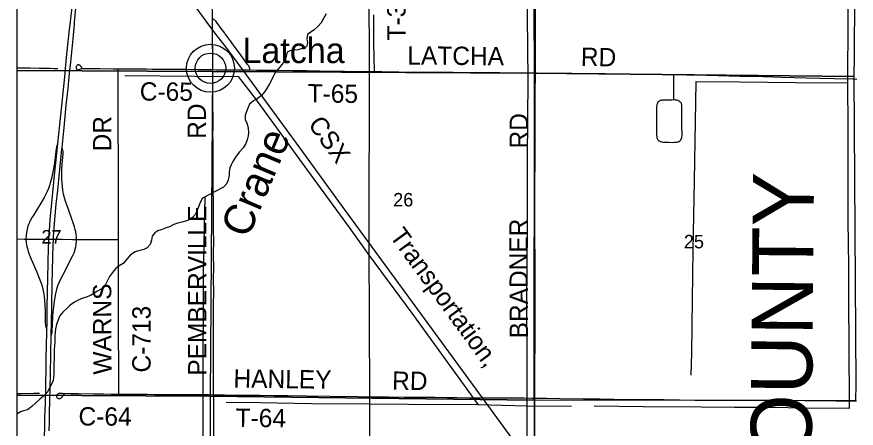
# Model space of a CAD drawing. Extents: x 0 to 34, y 0 to 22.
# Drawn here: x 2.1 to 4.702, y 15.265 to 16.541 of the extents above; entities that cross this region are included whole.
import ezdxf

# ---------------------------------------------------------------- set-up
doc = ezdxf.new("R2010")
doc.units = 0
for name, color, linetype in [('Default', 7, 'Continuous'), ('GM_X_County_Road', 7, 'Continuous'), ('GM_X_County_Road_Text', 7, 'Continuous'), ('GM_X_County_Text', 7, 'Continuous'), ('GM_X_Interchange_Ramps', 7, 'Continuous'), ('GM_X_Interstate_Route', 7, 'Continuous'), ('GM_X_Minor_River', 7, 'Continuous'), ('GM_X_Minor_River_Text', 7, 'Continuous'), ('GM_X_Rail_Line', 7, 'Continuous'), ('GM_X_Rail_Line_Text', 7, 'Continuous'), ('GM_X_Section', 7, 'Continuous'), ('GM_X_Section_Text', 7, 'Continuous'), ('GM_X_Township_Road', 7, 'Continuous'), ('GM_X_Township_Road_Text', 7, 'Continuous'), ('GM_X_Unincorporated', 7, 'Continuous'), ('GM_X_Unincorporated_Location', 7, 'Continuous'), ('GM_X_Unincorporated_Text', 7, 'Continuous')]:
    doc.layers.add(name, color=color, linetype=linetype)

msp = doc.modelspace()

# ---------------------------------------------------------------- linework, layer by layer
at = {"layer": 'Default'}
for points in [[(2.1, 17.3903), (2.1, 16.375), (2.7079, 16.3715), (2.7017, 17.3873)], [(2.1, 16.375), (2.1, 15.3673), (2.7001, 15.3638), (2.7079, 16.3715)], [(2.1, 15.3673), (2.1, 14.3654), (2.6651, 14.3602), (2.7019, 14.3602), (2.7001, 15.3638)]]:
    msp.add_lwpolyline(points, close=True, dxfattribs=at)
at = {"layer": 'GM_X_County_Road'}
for points in [[(2.7069, 16.5346), (2.7069, 16.5391), (2.7066, 16.5708)], [(2.7076, 16.3773), (2.7074, 16.4154), (2.7069, 16.467), (2.7066, 16.4956), (2.7067, 16.5062), (2.7069, 16.5161), (2.7069, 16.5346)], [(2.1, 16.3831), (2.1106, 16.3831), (2.1417, 16.3829), (2.1691, 16.3823), (2.1902, 16.3821), (2.2032, 16.3817), (2.2156, 16.3812), (2.2274, 16.3808)], [(2.3025, 16.3814), (2.3009, 16.3844), (2.2995, 16.3867), (2.2985, 16.3881), (2.297, 16.3898), (2.2956, 16.3908), (2.2941, 16.3915), (2.2925, 16.3919), (2.2908, 16.3919), (2.2892, 16.3915), (2.2877, 16.3908), (2.2864, 16.3898), (2.2853, 16.3886), (2.2844, 16.3871), (2.2838, 16.3855), (2.2836, 16.3839), (2.2837, 16.3823), (2.2841, 16.3813), (2.2845, 16.3805), (2.2853, 16.3796), (2.2864, 16.3787), (2.2878, 16.3779), (2.2894, 16.3774), (2.2909, 16.3773), (2.2927, 16.3774), (2.2949, 16.3779), (2.2966, 16.3787), (2.2981, 16.3795), (2.3002, 16.3806), (2.3021, 16.381), (2.3041, 16.3811), (2.308, 16.3812), (2.3128, 16.3812), (2.3235, 16.3812), (2.3446, 16.3808), (2.3583, 16.3805), (2.3993, 16.3802), (2.4145, 16.3801)], [(2.4154, 15.85), (2.4152, 15.9045), (2.415, 15.9897), (2.415, 16.0438), (2.4149, 16.1078), (2.4147, 16.185), (2.4146, 16.2465), (2.4144, 16.3317), (2.4145, 16.3697), (2.4145, 16.3801)], [(2.4145, 16.3801), (2.4316, 16.3799), (2.4538, 16.3797)], [(2.4538, 16.3797), (2.4739, 16.3796), (2.5006, 16.3794), (2.5211, 16.3793), (2.5659, 16.379), (2.5883, 16.3789), (2.6243, 16.3784), (2.6622, 16.3779), (2.6872, 16.3777), (2.7076, 16.3773)], [(2.7102, 15.3684), (2.7098, 15.3851), (2.7102, 15.4354), (2.7101, 15.4993), (2.7101, 15.5404), (2.71, 15.5833), (2.7103, 15.6475), (2.7106, 15.6878), (2.7102, 15.7257), (2.7104, 15.7667), (2.7103, 15.7985), (2.7105, 15.8544), (2.7103, 15.8675), (2.7102, 15.8868), (2.7103, 15.8986), (2.7099, 15.9272), (2.7096, 15.9693), (2.7093, 16.0015), (2.7089, 16.0178), (2.7085, 16.0544), (2.7089, 16.103), (2.7085, 16.1508), (2.7083, 16.1756), (2.7084, 16.198), (2.7085, 16.2323), (2.7082, 16.2596), (2.7079, 16.2926), (2.7078, 16.3087), (2.7076, 16.3199), (2.7076, 16.3553), (2.7076, 16.3773)], [(2.1, 15.8518), (2.1227, 15.8516), (2.1276, 15.8516)], [(2.1276, 15.8516), (2.1495, 15.8516), (2.1843, 15.8511), (2.1996, 15.8511), (2.2138, 15.851), (2.2402, 15.8509), (2.2731, 15.8507), (2.2855, 15.8507)], [(2.2855, 15.8507), (2.3005, 15.8506), (2.3408, 15.8503), (2.4154, 15.85)], [(2.416, 15.3705), (2.4161, 15.3796), (2.4161, 15.392), (2.4159, 15.4586), (2.4157, 15.555), (2.4157, 15.5935), (2.4156, 15.6906), (2.4157, 15.7328), (2.4154, 15.7614), (2.4156, 15.7813), (2.4155, 15.8242), (2.4154, 15.85)], [(2.1, 15.3724), (2.1134, 15.3724), (2.1519, 15.3732), (2.1657, 15.3734), (2.1706, 15.3735)], [(2.2478, 15.3723), (2.2473, 15.3716), (2.2432, 15.3657), (2.2418, 15.3638), (2.2399, 15.3611), (2.2378, 15.3585), (2.2366, 15.3573), (2.2353, 15.3564), (2.2337, 15.3558), (2.2321, 15.3555), (2.2305, 15.3557), (2.2289, 15.3562), (2.2275, 15.357), (2.2262, 15.3582), (2.2252, 15.3595), (2.2245, 15.3611), (2.2241, 15.3627), (2.224, 15.3644), (2.2242, 15.3661), (2.2248, 15.3677), (2.2256, 15.3691), (2.2266, 15.3704), (2.2279, 15.3714), (2.2294, 15.3722), (2.2316, 15.3729), (2.2346, 15.3732), (2.242, 15.3731), (2.2668, 15.3722), (2.2818, 15.3719), (2.2911, 15.3719), (2.3377, 15.3714), (2.3551, 15.3713), (2.37, 15.371), (2.3918, 15.3706), (2.416, 15.3705)], [(2.416, 15.3705), (2.4229, 15.3705), (2.4847, 15.3701)], [(2.4847, 15.3701), (2.5056, 15.37), (2.5274, 15.3696), (2.5821, 15.3695), (2.6461, 15.3691), (2.6716, 15.369), (2.6942, 15.3688), (2.708, 15.3684), (2.7102, 15.3684)], [(2.7076, 14.7538), (2.7078, 14.762), (2.7081, 14.8136), (2.7085, 14.8357), (2.7085, 14.8418), (2.7086, 14.8505), (2.7087, 14.8596), (2.7087, 14.865), (2.7088, 14.8824), (2.7089, 14.9074), (2.7092, 14.9316), (2.7091, 14.954), (2.7095, 14.9764), (2.7111, 15.064), (2.7116, 15.0914), (2.7115, 15.1045), (2.7116, 15.1337), (2.7116, 15.1902), (2.7112, 15.2413), (2.7105, 15.319), (2.7106, 15.3539), (2.7102, 15.3684)]]:
    msp.add_lwpolyline(points, dxfattribs=at)
at = {"layer": 'GM_X_Interchange_Ramps'}
for points in [[(2.227, 16.1478), (2.2252, 16.1439), (2.224, 16.1404), (2.2229, 16.1371), (2.222, 16.1329), (2.218, 16.0964), (2.2161, 16.0823), (2.214, 16.0701), (2.2109, 16.0548), (2.2072, 16.0391), (2.2039, 16.0265), (2.2015, 16.0182), (2.1982, 16.0088), (2.1945, 15.9996), (2.1904, 15.9905), (2.185, 15.9801), (2.1777, 15.9678), (2.1597, 15.9388), (2.1525, 15.9271), (2.1476, 15.9191), (2.1425, 15.9104), (2.1407, 15.9068)], [(2.2855, 15.8507), (2.2848, 15.8583), (2.2841, 15.8664), (2.283, 15.8738), (2.2813, 15.8817), (2.2792, 15.8894), (2.276, 15.8989), (2.2609, 15.9397), (2.2547, 15.9573), (2.251, 15.9691), (2.248, 15.9799), (2.2453, 15.9914), (2.2431, 16.0037), (2.2416, 16.0147), (2.2405, 16.0259), (2.2398, 16.0383), (2.2396, 16.0513), (2.24, 16.0663), (2.241, 16.0843), (2.2435, 16.1165), (2.2436, 16.1196), (2.2434, 16.1233), (2.2428, 16.1271), (2.2417, 16.1316), (2.2403, 16.136)], [(2.1407, 15.9068), (2.139, 15.9033), (2.1363, 15.8966), (2.1337, 15.8888), (2.1317, 15.881), (2.1299, 15.8718), (2.1286, 15.8631), (2.1276, 15.8516)], [(2.1276, 15.8516), (2.129, 15.8402), (2.1298, 15.834), (2.1309, 15.8285), (2.1327, 15.8219), (2.1356, 15.8131), (2.1386, 15.8049), (2.1418, 15.7968), (2.1522, 15.7729), (2.1619, 15.7493), (2.1719, 15.7246), (2.1753, 15.7152), (2.1782, 15.7057), (2.1807, 15.6961), (2.1828, 15.6858), (2.1848, 15.6735), (2.1863, 15.6605), (2.1871, 15.6463), (2.1876, 15.6276), (2.1881, 15.5916), (2.1891, 15.5836), (2.19, 15.5796), (2.1911, 15.5759), (2.1933, 15.5697)], [(2.271, 15.7949), (2.2751, 15.803), (2.2777, 15.8089), (2.2797, 15.8145), (2.2815, 15.8212), (2.2831, 15.8279), (2.2843, 15.8346), (2.2852, 15.8443), (2.2855, 15.8507)], [(2.2067, 15.5518), (2.209, 15.5578), (2.2098, 15.5618), (2.2102, 15.5662), (2.211, 15.5872), (2.2119, 15.6083), (2.2131, 15.6251), (2.2148, 15.6412), (2.2169, 15.6578), (2.219, 15.6713), (2.2212, 15.6829), (2.2233, 15.6914), (2.2256, 15.6998), (2.2288, 15.7092), (2.2327, 15.719), (2.237, 15.7286), (2.2435, 15.7414), (2.2575, 15.7677), (2.271, 15.7949)]]:
    msp.add_lwpolyline(points, dxfattribs=at)
at = {"layer": 'GM_X_Interstate_Route'}
for points in [[(4.7088, 20.9), (2.1, 20.9), (2.1, 14.3639)], [(2.2664, 16.5242), (2.2678, 16.5361), (2.2863, 16.6892), (2.2911, 16.7324), (2.2947, 16.7671), (2.2976, 16.7949), (2.3097, 16.9117), (2.3139, 16.9538), (2.3177, 16.9909), (2.3235, 17.0459), (2.3279, 17.0899), (2.3333, 17.1443), (2.3431, 17.237), (2.3464, 17.2717), (2.3468, 17.2766)], [(2.2787, 16.5175), (2.2794, 16.5245), (2.2831, 16.5685), (2.2888, 16.6361), (2.2917, 16.6695), (2.2939, 16.6937), (2.2993, 16.7519), (2.3027, 16.7865), (2.3057, 16.8156), (2.3146, 16.8996), (2.3198, 16.9503), (2.3242, 16.9943), (2.3297, 17.0493), (2.3341, 17.0926), (2.3388, 17.1365), (2.3464, 17.2113), (2.352, 17.2639), (2.3534, 17.2758)], [(2.1857, 15.2086), (2.1874, 15.2981), (2.1885, 15.3416), (2.1899, 15.4001), (2.1909, 15.4492), (2.1914, 15.4902), (2.1919, 15.5126), (2.1933, 15.5697), (2.1938, 15.5903), (2.1942, 15.6089), (2.1945, 15.6319), (2.1957, 15.6947), (2.1962, 15.7227), (2.1974, 15.7855), (2.1982, 15.8178), (2.1996, 15.8511), (2.2011, 15.8786), (2.2035, 15.9121), (2.2061, 15.9418), (2.2167, 16.0501), (2.2209, 16.0884), (2.227, 16.1478), (2.233, 16.2065), (2.2495, 16.3658), (2.2499, 16.3692), (2.2556, 16.4255), (2.2637, 16.5015), (2.2664, 16.5242)], [(2.2007, 15.2563), (2.2012, 15.285), (2.2018, 15.3117), (2.2034, 15.3919), (2.2043, 15.431), (2.2054, 15.4957), (2.2067, 15.5518), (2.2077, 15.5926), (2.2087, 15.6442), (2.2101, 15.7132), (2.2119, 15.7947), (2.213, 15.8332), (2.2138, 15.851), (2.2142, 15.8587), (2.2161, 15.8879), (2.2189, 15.9238), (2.2223, 15.9598), (2.227, 16.003), (2.2304, 16.0339), (2.2348, 16.0791), (2.2396, 16.1292), (2.2403, 16.136), (2.2466, 16.1973), (2.2536, 16.2672), (2.2589, 16.3185), (2.2639, 16.3659), (2.2676, 16.4008), (2.2745, 16.4725), (2.2787, 16.5175)]]:
    msp.add_lwpolyline(points, dxfattribs=at)
at = {"layer": 'GM_X_Minor_River'}
for points in [[(3.6785, 17.0216), (3.6816, 16.7654), (3.6827, 16.5423), (3.6841, 16.3464), (3.6825, 16.1017), (3.6821, 15.8805), (3.6804, 15.6582), (3.6808, 15.4396), (3.6814, 15.3334), (3.6828, 15.1345), (3.683, 15.0055), (3.6833, 14.8112), (3.6833, 14.6667)], [(4.7006, 17.0285), (4.6915, 17.0258), (4.6859, 17.0213), (4.6828, 17.0141), (4.6803, 17.002), (4.6792, 16.9527), (4.6799, 16.81), (4.6773, 16.6662), (4.6768, 16.4928), (4.6751, 16.3793), (4.6751, 16.3346), (4.6764, 16.1979), (4.6763, 16.0257), (4.6763, 15.9088), (4.6786, 15.7672), (4.6786, 15.6466), (4.6794, 15.5312), (4.6803, 15.3255), (4.5472, 15.3266), (4.4349, 15.3284), (4.3256, 15.329), (4.2223, 15.3295), (4.0419, 15.3313), (3.8902, 15.3326)], [(3.1937, 14.6594), (3.1937, 14.9), (3.1943, 15.1508), (3.1942, 15.339), (3.1938, 15.6247), (3.1921, 15.8008), (3.1928, 16.0148), (3.1938, 16.2242), (3.194, 16.3798), (3.1923, 16.6356), (3.1907, 16.6743), (3.1894, 16.725)], [(3.059, 16.5508), (3.0504, 16.5365), (3.0438, 16.5226), (3.0334, 16.511), (3.0223, 16.501), (3.0116, 16.4935), (3.0016, 16.4861), (2.9991, 16.4729), (3.0008, 16.4607), (2.998, 16.4486), (2.9847, 16.4427), (2.9725, 16.4391), (2.9619, 16.4374), (2.9501, 16.4368), (2.9383, 16.4317), (2.9355, 16.4189), (2.9319, 16.406), (2.9222, 16.3929), (2.9103, 16.379), (2.9002, 16.3659), (2.8944, 16.3562), (2.8885, 16.343), (2.8834, 16.3328), (2.8776, 16.3227), (2.8694, 16.3099), (2.8587, 16.2972), (2.8456, 16.2871), (2.8334, 16.2801), (2.8219, 16.27), (2.8161, 16.258), (2.8113, 16.2448), (2.8081, 16.235), (2.8079, 16.2225), (2.8141, 16.2091), (2.8173, 16.1961), (2.8179, 16.1813), (2.8173, 16.1715), (2.8145, 16.159), (2.8102, 16.1484), (2.802, 16.1345), (2.7908, 16.1226), (2.78, 16.1087), (2.7696, 16.0925), (2.7649, 16.082), (2.7605, 16.0722), (2.7584, 16.059), (2.7583, 16.0495), (2.7558, 16.0351), (2.7507, 16.0245), (2.7411, 16.0129), (2.6762, 15.9787), (2.6688, 15.9652), (2.6629, 15.952), (2.659, 15.941), (2.6539, 15.9293), (2.6446, 15.9185), (2.6324, 15.91), (2.6229, 15.9071), (2.6122, 15.9035), (2.5997, 15.9014), (2.5864, 15.8967), (2.573, 15.8893), (2.5632, 15.8864), (2.5476, 15.8802), (2.5377, 15.8766), (2.5281, 15.8707), (2.5193, 15.8609), (2.5172, 15.8477), (2.5132, 15.8349), (2.5043, 15.8248), (2.494, 15.8196), (2.4773, 15.8146), (2.4667, 15.8117), (2.4525, 15.8021), (2.4302, 15.7759), (2.4179, 15.7689), (2.4064, 15.7588), (2.3964, 15.7476), (2.3879, 15.7356), (2.3813, 15.7232), (2.375, 15.7104), (2.3642, 15.6984), (2.3505, 15.6899), (2.339, 15.6825), (2.3287, 15.6766), (2.3146, 15.6715), (2.3047, 15.6682), (2.2907, 15.6624), (2.2792, 15.6554)], [(2.4352, 16.359), (2.6534, 16.357), (2.7866, 16.356), (2.8392, 16.2876), (3.0014, 16.0645), (3.1306, 15.8879), (3.1921, 15.8008), (3.3243, 15.6214), (3.4435, 15.4567), (3.5309, 15.3366)], [(4.6759, 16.3349), (4.5147, 16.3368), (4.3411, 16.3381), (4.2049, 16.3391), (4.203, 16.2162), (4.2001, 16.0326), (4.1959, 15.8175), (4.1939, 15.6639), (4.1917, 15.4981), (4.1902, 15.4291)], [(2.6723, 14.3408), (2.6826, 14.3691), (2.6813, 14.5774), (2.6793, 14.9534), (2.6777, 15.2084), (2.6779, 15.3894), (2.6785, 15.7411), (2.6841, 15.9829)], [(2.2792, 15.6554), (2.2658, 15.6465), (2.2558, 15.6375), (2.2432, 15.6244), (2.2324, 15.6121), (2.228, 15.6012), (2.2236, 15.5868), (2.2204, 15.5725), (2.2187, 15.5615), (2.2182, 15.5512), (2.2177, 15.5433), (2.2175, 15.5327), (2.2169, 15.5205), (2.2164, 15.5092), (2.2144, 15.4341), (2.2139, 15.4238), (2.2133, 15.4121), (2.1942, 15.3752), (2.1827, 15.3644), (2.1715, 15.3543), (2.1593, 15.3431), (2.1462, 15.332), (2.1332, 15.3219), (2.1207, 15.3187), (2.1112, 15.3158), (2.1, 15.3083)], [(3.8194, 15.3323), (3.6814, 15.3334), (3.5309, 15.3366), (3.3145, 15.3382), (3.1942, 15.339), (3.0142, 15.3407), (2.855, 15.3433), (2.7494, 15.3439)]]:
    msp.add_lwpolyline(points, dxfattribs=at)
at = {"layer": 'GM_X_Rail_Line'}
msp.add_lwpolyline([(4.4636, 14.1), (4.2829, 14.3475), (4.0202, 14.7061), (3.9178, 14.8467), (3.7641, 15.0572), (3.5439, 15.3588), (3.2112, 15.8143), (3.0989, 15.9678), (2.9869, 16.1219), (2.8009, 16.3767), (2.7485, 16.4478), (2.7239, 16.4783), (2.6984, 16.5122), (2.4472, 16.8567), (2.3237, 17.0297), (2.1, 17.3362)], dxfattribs=at)
at = {"layer": 'GM_X_Section'}
for points in [[(3.7003, 17.3796), (3.7046, 16.3661), (2.7079, 16.3715), (2.7017, 17.3873)], [(4.6959, 16.4195), (4.6953, 16.3562), (3.7046, 16.3661), (3.7003, 17.3796), (4.7018, 17.3475)], [(2.7079, 16.3715), (3.7046, 16.3661), (3.7036, 15.3519), (2.7001, 15.3638)], [(3.7046, 16.3661), (4.6953, 16.3562), (4.7008, 15.401), (4.7006, 15.3495), (3.7036, 15.3519)], [(3.7036, 15.3519), (3.7061, 14.3445), (3.6799, 14.3459), (2.7019, 14.3602), (2.7001, 15.3638)]]:
    msp.add_lwpolyline(points, close=True, dxfattribs=at)
at = {"layer": 'GM_X_Township_Road'}
for points in [[(3.7078, 16.3671), (3.7078, 16.3913), (3.708, 16.4435), (3.7083, 16.4877), (3.7081, 16.5778), (3.7078, 16.6593), (3.7076, 16.7091), (3.7074, 16.7644), (3.7071, 16.8378), (3.707, 16.8988), (3.707, 16.9516), (3.7063, 17.0194), (3.7057, 17.0399), (3.7048, 17.0859), (3.7046, 17.1244), (3.7037, 17.2457), (3.7031, 17.3184)], [(2.823, 16.3764), (2.8225, 16.3789), (2.8221, 16.3813), (2.8214, 16.3836), (2.8204, 16.3861), (2.8189, 16.3887), (2.8173, 16.3911), (2.8155, 16.3938), (2.8104, 16.4009), (2.7955, 16.4209), (2.7749, 16.449), (2.7718, 16.4533), (2.7692, 16.457), (2.7625, 16.4663), (2.7603, 16.4693), (2.7586, 16.4717), (2.755, 16.4765), (2.7463, 16.4882), (2.7446, 16.4904), (2.7341, 16.5048), (2.7206, 16.5235), (2.718, 16.5269), (2.716, 16.5292), (2.7138, 16.5312), (2.712, 16.5323), (2.7095, 16.5335), (2.7069, 16.5346)], [(3.2087, 16.3713), (3.2086, 16.3779), (3.2079, 16.4109), (3.2071, 16.4651), (3.2068, 16.5473)], [(2.7076, 16.3773), (2.7169, 16.3772), (2.7453, 16.377), (2.777, 16.3767), (2.792, 16.3766), (2.8, 16.3766), (2.8174, 16.3765), (2.823, 16.3764)], [(2.823, 16.3764), (2.8442, 16.3761), (2.9051, 16.3755), (2.9555, 16.3748), (2.9978, 16.3744), (3.0388, 16.3736), (3.1942, 16.3714), (3.2087, 16.3713)], [(3.2087, 16.3713), (3.2315, 16.3711), (3.2844, 16.3707), (3.3851, 16.3698), (3.4057, 16.3699), (3.4249, 16.3696), (3.4529, 16.3691), (3.4884, 16.3688), (3.5213, 16.3685), (3.5506, 16.3685), (3.5792, 16.3681), (3.5966, 16.368), (3.6737, 16.3673), (3.701, 16.3672), (3.7078, 16.3671)], [(3.7061, 15.3581), (3.7061, 15.3615), (3.7059, 15.3876), (3.7063, 15.4175), (3.7065, 15.4366), (3.7064, 15.467), (3.7069, 15.5224), (3.7068, 15.551), (3.7068, 15.5969), (3.707, 15.6565), (3.7071, 15.7056), (3.7069, 15.7329), (3.707, 15.7566), (3.7067, 15.8131), (3.7066, 15.8299), (3.7064, 15.8629), (3.7065, 15.8884), (3.7064, 15.9282), (3.7064, 15.9798), (3.7066, 16.037), (3.7067, 16.0842), (3.7069, 16.1178), (3.7072, 16.175), (3.7074, 16.2067), (3.7073, 16.262), (3.7076, 16.3217), (3.7079, 16.3473), (3.7078, 16.3648), (3.7078, 16.3671)], [(3.7078, 16.3671), (3.711, 16.3671), (3.729, 16.3669), (3.7819, 16.3663), (3.8204, 16.366), (3.8559, 16.3657), (3.8919, 16.3653), (3.9249, 16.365), (3.9696, 16.3644), (3.9995, 16.364), (4.0281, 16.3637), (4.0548, 16.3633), (4.1102, 16.3627), (4.1369, 16.3622)], [(4.1369, 16.3622), (4.1773, 16.3614), (4.2016, 16.361), (4.2743, 16.3595), (4.3415, 16.3576), (4.3868, 16.3566), (4.4714, 16.3543), (4.5472, 16.3522), (4.6343, 16.35), (4.6922, 16.3484), (4.6964, 16.3483), (4.704, 16.3481)], [(4.1373, 16.2832), (4.1373, 16.2878), (4.1373, 16.2921), (4.1373, 16.2957), (4.1375, 16.3104), (4.1372, 16.3241), (4.1371, 16.3354), (4.1371, 16.3454), (4.1369, 16.3537), (4.1369, 16.3609), (4.1369, 16.3622)], [(4.1373, 16.2832), (4.1312, 16.283), (4.1259, 16.2828), (4.1205, 16.2826), (4.1156, 16.2826), (4.1021, 16.2826), (4.0998, 16.2824), (4.0977, 16.282), (4.0963, 16.2816), (4.0949, 16.2811), (4.0932, 16.2804), (4.0915, 16.2795), (4.0901, 16.2786), (4.0893, 16.2779), (4.0886, 16.2771), (4.0879, 16.2762), (4.0869, 16.2746), (4.0859, 16.2727), (4.0854, 16.2715), (4.0847, 16.2692), (4.0841, 16.2657), (4.0838, 16.2614), (4.0837, 16.2575), (4.0837, 16.2526), (4.0835, 16.2357), (4.0835, 16.2255), (4.0836, 16.2172), (4.0835, 16.2008), (4.0834, 16.184), (4.0833, 16.1796), (4.0834, 16.1766), (4.0836, 16.1742), (4.084, 16.1694), (4.0846, 16.1664), (4.0855, 16.1636), (4.0865, 16.1616), (4.0874, 16.1601), (4.0884, 16.1588), (4.0893, 16.1578), (4.0904, 16.1569), (4.0917, 16.1559), (4.0935, 16.155), (4.0957, 16.1541), (4.0985, 16.1532), (4.1021, 16.1527), (4.1062, 16.1524), (4.1108, 16.1521), (4.1213, 16.1518)], [(4.1213, 16.1518), (4.1314, 16.1517), (4.1388, 16.1518), (4.145, 16.1523), (4.1486, 16.1528), (4.1514, 16.1536), (4.1541, 16.1548), (4.1561, 16.1561), (4.1576, 16.1576), (4.1589, 16.1594), (4.1602, 16.1618), (4.1612, 16.1644), (4.162, 16.1672), (4.1623, 16.169), (4.1626, 16.1725), (4.1626, 16.1765), (4.1623, 16.2001), (4.1623, 16.2138), (4.1623, 16.23), (4.1622, 16.2327), (4.1623, 16.2475), (4.1622, 16.263), (4.1621, 16.2662), (4.1617, 16.2685), (4.1612, 16.2701), (4.1605, 16.272), (4.1595, 16.2739), (4.1587, 16.2751), (4.1572, 16.2765), (4.1555, 16.278), (4.1537, 16.2793), (4.1515, 16.2807), (4.149, 16.2817), (4.1464, 16.2823), (4.1437, 16.2828), (4.1407, 16.283), (4.1373, 16.2832)], [(2.7102, 15.3684), (2.7233, 15.3684), (2.7443, 15.3681), (2.776, 15.3676), (2.8039, 15.3674), (2.8543, 15.3667), (2.8978, 15.3663), (2.9407, 15.3656), (2.9985, 15.3649), (3.0706, 15.3641), (3.1582, 15.3631), (3.1862, 15.3624), (3.2116, 15.3619), (3.2539, 15.3617), (3.3012, 15.3611), (3.3478, 15.3609), (3.3521, 15.3609), (3.3564, 15.3609), (3.3589, 15.3609), (3.3645, 15.3609), (3.3689, 15.3608), (3.3744, 15.3608), (3.3968, 15.3606), (3.4347, 15.36), (3.4552, 15.3597), (3.4639, 15.3596), (3.5041, 15.3591), (3.5215, 15.359), (3.5377, 15.3592), (3.5445, 15.3593), (3.5544, 15.3593), (3.5694, 15.3592), (3.593, 15.3592), (3.6458, 15.3585), (3.6725, 15.3584), (3.6964, 15.3581), (3.7061, 15.3581)], [(3.7061, 15.1936), (3.7063, 15.2701), (3.7062, 15.3254), (3.7061, 15.3581)], [(3.7061, 15.3581), (3.7077, 15.3581), (3.7448, 15.3577), (3.7834, 15.357), (3.8567, 15.3561), (3.9089, 15.3556), (3.9506, 15.355), (4.0705, 15.3536), (4.1072, 15.3532), (4.2017, 15.352), (4.2427, 15.3518), (4.2819, 15.3515), (4.3198, 15.3513), (4.3639, 15.3511), (4.4031, 15.3511), (4.436, 15.3512), (4.4745, 15.3511), (4.5435, 15.3506), (4.5839, 15.3504), (4.6398, 15.3499), (4.6907, 15.3493), (4.7029, 15.3493), (4.7038, 15.3493)]]:
    msp.add_lwpolyline(points, dxfattribs=at)
at = {"layer": 'GM_X_Unincorporated'}
for radius in [0.0744, 0.0472]:
    msp.add_circle((2.7005, 16.3816), radius, dxfattribs=at)
at = {"layer": 'GM_X_Unincorporated_Location'}
msp.add_line((2.7005, 16.3816), (2.7005, 16.3816), dxfattribs=at)

# ---------------------------------------------------------------- texts
at = {"layer": 'GM_X_County_Road_Text'}
for s, height, rotation, p in [('C-65', 0.05682, 359.6614, (2.4812, 16.2814)), ('RD', 0.05682, 90, (2.6863, 16.1626)), ('DR', 0.05682, 90, (2.393, 16.1235)), ('PEMBERVILLE', 0.056818, 90, (2.688, 15.4276)), ('WARNS', 0.05682, 90.1914, (2.3938, 15.4308)), ('C-713', 0.05682, 89.999, (2.5149, 15.4374)), ('C-64', 0.05682, 359.6575, (2.2912, 15.2731))]:
    msp.add_text(s, height=height, rotation=rotation, dxfattribs=at).set_placement(p)
at = {"layer": 'GM_X_County_Text'}
msp.add_text('WOOD COUNTY', height=0.189394, rotation=89.499, dxfattribs=at).set_placement((4.5547, 14.1029))
at = {"layer": 'GM_X_Minor_River_Text'}
msp.add_text('Crane', height=0.09476, rotation=67.1977, dxfattribs=at).set_placement((2.8168, 15.8506))
at = {"layer": 'GM_X_Rail_Line_Text'}
for s, height, rotation, p in [('CSX', 0.05663, 305.8148, (3.001, 16.2075)), ('Transportation,', 0.056629, 306.1138, (3.2539, 15.8604))]:
    msp.add_text(s, height=height, rotation=rotation, dxfattribs=at).set_placement(p)
at = {"layer": 'GM_X_Section_Text'}
for s, p in [('26', (3.267, 15.9527)), ('27', (2.1766, 15.8377)), ('25', (4.1682, 15.8227))]:
    msp.add_text(s, height=0.04186, rotation=0, dxfattribs=at).set_placement(p)
at = {"layer": 'GM_X_Township_Road_Text'}
for s, rotation, p in [('T-316', 90.2805, (3.3056, 16.4682)), ('LATCHA', 359.4946, (3.3106, 16.3933)), ('RD', 359.0187, (3.8484, 16.3891)), ('T-65', 359.2904, (3.0015, 16.2757)), ('RD', 90, (3.6848, 16.1326)), ('BRADNER', 90.143, (3.6848, 15.5434)), ('HANLEY', 359.3348, (2.7715, 15.3906)), ('RD', 359.5121, (3.2635, 15.3839)), ('T-64', 359.2939, (2.7781, 15.269))]:
    msp.add_text(s, height=0.05682, rotation=rotation, dxfattribs=at).set_placement(p)
at = {"layer": 'GM_X_Unincorporated_Text'}
msp.add_text('Latcha', height=0.07898, rotation=0, dxfattribs=at).set_placement((2.7995, 16.3976))

doc.saveas('drawing.dxf')
